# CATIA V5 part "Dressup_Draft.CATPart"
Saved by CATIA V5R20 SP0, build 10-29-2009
Part number: Part1
Bounding box of the stored display mesh (mm): x -50.415 to 49.634, y -49.137 to 46.791, z -43 to 43
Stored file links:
  G:\카티아자료\수업자료\툴바예제\2 PartDesign\Dressup_Draft.CATPart
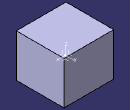
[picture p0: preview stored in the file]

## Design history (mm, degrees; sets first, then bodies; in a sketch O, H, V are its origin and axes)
AxisSystem1: origin (0, 0, 0), X (1, 0, 0), Y (0, 1, 0), Z (0, 0, 1)
Body1 (main body)
  Sketch1 on XY plane of AxisSystem1, origin (0, 0, 0), H (1, 0, 0), V (0, 1, 0)
    line L1 (-50.4152, 46.7906) -> (49.6336, 46.7906)
    line L2 (49.6336, 46.7906) -> (49.6336, -49.1366)
    line L3 (49.6336, -49.1366) -> (-50.4152, -49.1366)
    line L4 (-50.4152, -49.1366) -> (-50.4152, 46.7906)
    horizontal: L1 H, L3 H
    vertical: L2 V, L4 V
  Pad1: profile Sketch1, direction (0, 0, 1), length 43, mirrored extent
